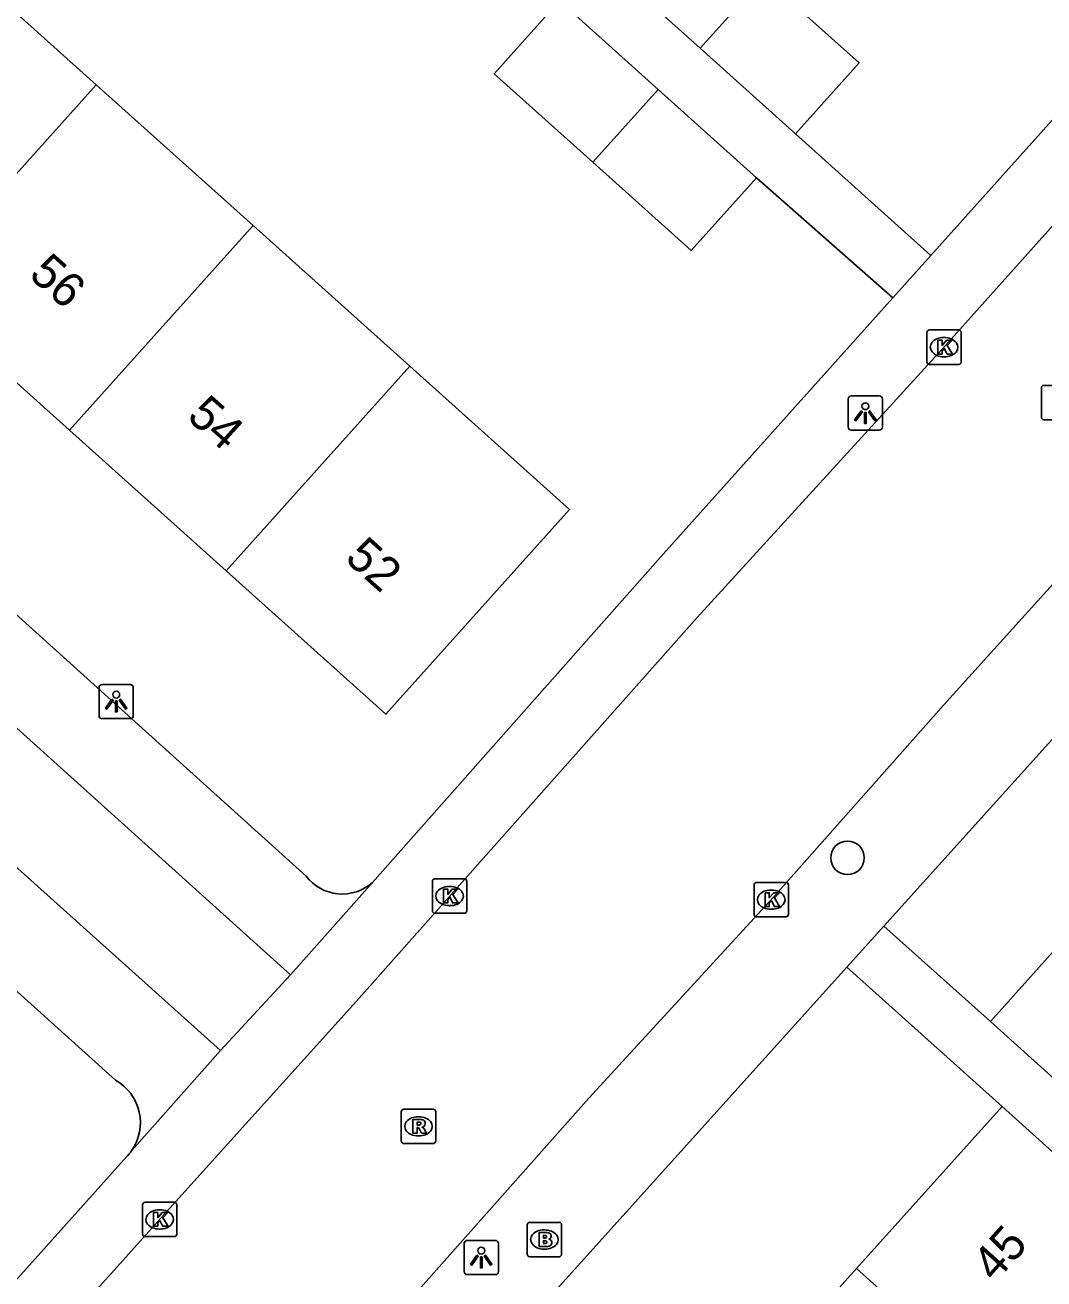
# Model space of a CAD drawing. Extents: x 159040 to 160094, y 381214 to 382518.
# Drawn here: x 159439.83 to 159469.45, y 382064.07 to 382100.53 of the extents above; entities that cross this region are included whole.
import ezdxf

# ---------------------------------------------------------------- set-up
doc = ezdxf.new("R2010")
doc.units = 0
for name, color, linetype in [('IMGEO_Boom', 7, 'Continuous'), ('IMGEO_Brandkraan', 7, 'Continuous'), ('IMGEO_Kolk', 7, 'Continuous'), ('IMGEO_Lichtpunt', 7, 'Continuous'), ('IMGEO_Pand', 7, 'Continuous'), ('IMGEO_Pand_nummerreeks', 7, 'Continuous'), ('IMGEO_Rijbaan_lokaal_open', 7, 'Continuous'), ('IMGEO_Rioolput', 7, 'Continuous'), ('IMGEO_Voetpad_open', 7, 'Continuous')]:
    doc.layers.add(name, color=color, linetype=linetype)

msp = doc.modelspace()

# ---------------------------------------------------------------- linework, layer by layer
at = {"layer": 'IMGEO_Boom'}
msp.add_circle((159463.742, 382076.312), 0.489, dxfattribs=at)
at = {"layer": 'IMGEO_Brandkraan'}
for p, q in [((159454.427, 382064.787), (159454.427, 382065.639)), ((159454.502, 382065.713), (159455.354, 382065.713)), ((159455.428, 382065.639), (159455.428, 382064.787)), ((159454.915, 382065.493), (159454.94, 382065.493)), ((159454.938, 382064.933), (159454.913, 382064.933)), ((159455.354, 382064.713), (159454.502, 382064.713))]:
    msp.add_line(p, q, dxfattribs=at)
for points in [[(159454.427, 382064.787), (159454.427, 382065.639)], [(159454.502, 382065.713), (159455.354, 382065.713)], [(159455.428, 382065.639), (159455.428, 382064.787)], [(159454.775, 382065.413), (159454.775, 382065.013), (159454.988, 382065.013)], [(159455.006, 382065.413), (159454.775, 382065.413)], [(159454.954, 382065.332), (159454.9, 382065.332), (159454.9, 382065.256)], [(159454.9, 382065.256), (159454.953, 382065.256)], [(159454.962, 382065.18), (159454.9, 382065.18), (159454.9, 382065.099)], [(159454.9, 382065.099), (159454.962, 382065.099)], [(159455.354, 382064.713), (159454.502, 382064.713)]]:
    msp.add_lwpolyline(points, dxfattribs=at)
for centre, radius, start, end in [((159454.504, 382065.637), 0.0765, 91.552, 178.448), ((159454.504, 382065.637), 0.0765, 91.552, 178.448), ((159455.352, 382065.637), 0.0765, 1.552, 88.448), ((159455.352, 382065.637), 0.0765, 1.552, 88.448), ((159454.955, 382065.294), 0.0379, 267.8285, 90.9355), ((159455.01, 382065.268), 0.145, 59.4692, 91.5367), ((159455.035, 382065.315), 0.0922, 285.5137, 58.1501), ((159455.04, 382065.123), 0.105, 301.3115, 78.989), ((159454.963, 382065.139), 0.0404, 269.8759, 90.5077), ((159454.994, 382065.264), 0.251, 268.6676, 293.5347), ((159454.504, 382064.789), 0.0765, 181.552, 268.448), ((159454.504, 382064.789), 0.0765, 181.552, 268.448), ((159455.352, 382064.789), 0.0765, 271.552, 358.448), ((159455.352, 382064.789), 0.0765, 271.552, 358.448)]:
    msp.add_arc(centre, radius, start, end, dxfattribs=at)
for centre, major_axis, ratio, start_param, end_param in [((159454.914, 382065.213), (-0.387, 0.002), 0.722429, 4.712389, 7.853982), ((159454.939, 382065.213), (-0.39, 0.002), 0.717154, 1.570796, 4.712389)]:
    msp.add_ellipse(centre, major_axis=major_axis, ratio=ratio, start_param=start_param, end_param=end_param, dxfattribs=at)
at = {"layer": 'IMGEO_Kolk'}
for p, q in [((159466.049, 382090.735), (159466.049, 382091.587)), ((159466.124, 382091.661), (159466.976, 382091.661)), ((159466.537, 382091.441), (159466.562, 382091.441)), ((159467.05, 382091.587), (159467.05, 382090.735)), ((159466.56, 382090.881), (159466.535, 382090.881)), ((159466.976, 382090.661), (159466.124, 382090.661)), ((159451.671, 382074.775), (159451.671, 382075.627)), ((159451.746, 382075.701), (159452.598, 382075.701)), ((159452.159, 382075.481), (159452.184, 382075.481)), ((159452.672, 382075.627), (159452.672, 382074.775)), ((159461.023, 382074.67), (159461.023, 382075.522)), ((159461.098, 382075.596), (159461.95, 382075.596)), ((159462.024, 382075.522), (159462.024, 382074.67)), ((159461.511, 382075.376), (159461.536, 382075.376)), ((159452.598, 382074.701), (159451.746, 382074.701)), ((159452.182, 382074.921), (159452.157, 382074.921)), ((159461.534, 382074.816), (159461.509, 382074.816)), ((159461.95, 382074.596), (159461.098, 382074.596)), ((159443.314, 382066.297), (159444.166, 382066.297)), ((159443.239, 382065.371), (159443.239, 382066.223)), ((159443.727, 382066.077), (159443.752, 382066.077)), ((159444.24, 382066.223), (159444.24, 382065.371)), ((159444.166, 382065.297), (159443.314, 382065.297)), ((159443.75, 382065.517), (159443.725, 382065.517))]:
    msp.add_line(p, q, dxfattribs=at)
for points in [[(159466.049, 382090.735), (159466.049, 382091.587)], [(159466.124, 382091.661), (159466.976, 382091.661)], [(159467.05, 382091.587), (159467.05, 382090.735)], [(159466.37, 382091.361), (159466.493, 382091.361), (159466.493, 382091.21), (159466.623, 382091.361), (159466.787, 382091.361), (159466.641, 382091.21), (159466.794, 382090.961), (159466.642, 382090.961), (159466.557, 382091.125), (159466.493, 382091.058), (159466.493, 382090.961), (159466.37, 382090.961), (159466.37, 382091.361)], [(159466.976, 382090.661), (159466.124, 382090.661)], [(159451.671, 382074.775), (159451.671, 382075.627)], [(159451.746, 382075.701), (159452.598, 382075.701)], [(159451.992, 382075.401), (159452.115, 382075.401), (159452.115, 382075.25), (159452.245, 382075.401), (159452.409, 382075.401), (159452.263, 382075.25), (159452.416, 382075.001), (159452.264, 382075.001), (159452.179, 382075.165), (159452.115, 382075.098), (159452.115, 382075.001), (159451.992, 382075.001), (159451.992, 382075.401)], [(159452.672, 382075.627), (159452.672, 382074.775)], [(159461.023, 382074.67), (159461.023, 382075.522)], [(159461.098, 382075.596), (159461.95, 382075.596)], [(159462.024, 382075.522), (159462.024, 382074.67)], [(159461.344, 382075.296), (159461.467, 382075.296), (159461.467, 382075.145), (159461.597, 382075.296), (159461.761, 382075.296), (159461.615, 382075.145), (159461.768, 382074.896), (159461.616, 382074.896), (159461.531, 382075.06), (159461.467, 382074.993), (159461.467, 382074.896), (159461.344, 382074.896), (159461.344, 382075.296)], [(159452.598, 382074.701), (159451.746, 382074.701)], [(159461.95, 382074.596), (159461.098, 382074.596)], [(159443.314, 382066.297), (159444.166, 382066.297)], [(159443.239, 382065.371), (159443.239, 382066.223)], [(159443.56, 382065.997), (159443.683, 382065.997), (159443.683, 382065.846), (159443.813, 382065.997), (159443.977, 382065.997), (159443.831, 382065.846), (159443.984, 382065.597), (159443.832, 382065.597), (159443.747, 382065.761), (159443.683, 382065.694), (159443.683, 382065.597), (159443.56, 382065.597), (159443.56, 382065.997)], [(159444.24, 382066.223), (159444.24, 382065.371)], [(159444.166, 382065.297), (159443.314, 382065.297)]]:
    msp.add_lwpolyline(points, dxfattribs=at)
for centre, start, end in [((159466.126, 382091.585), 91.552, 178.448), ((159466.126, 382091.585), 91.552, 178.448), ((159466.974, 382091.585), 1.552, 88.448), ((159466.974, 382091.585), 1.552, 88.448), ((159466.126, 382090.737), 181.552, 268.448), ((159466.126, 382090.737), 181.552, 268.448), ((159466.974, 382090.737), 271.552, 358.448), ((159466.974, 382090.737), 271.552, 358.448), ((159451.748, 382075.625), 91.552, 178.448), ((159451.748, 382075.625), 91.552, 178.448), ((159452.596, 382075.625), 1.552, 88.448), ((159452.596, 382075.625), 1.552, 88.448), ((159461.1, 382075.52), 91.552, 178.448), ((159461.1, 382075.52), 91.552, 178.448), ((159461.948, 382075.52), 1.552, 88.448), ((159461.948, 382075.52), 1.552, 88.448), ((159451.748, 382074.777), 181.552, 268.448), ((159451.748, 382074.777), 181.552, 268.448), ((159452.596, 382074.777), 271.552, 358.448), ((159452.596, 382074.777), 271.552, 358.448), ((159461.1, 382074.672), 181.552, 268.448), ((159461.1, 382074.672), 181.552, 268.448), ((159461.948, 382074.672), 271.552, 358.448), ((159461.948, 382074.672), 271.552, 358.448), ((159443.316, 382066.221), 91.552, 178.448), ((159443.316, 382066.221), 91.552, 178.448), ((159444.164, 382066.221), 1.552, 88.448), ((159444.164, 382066.221), 1.552, 88.448), ((159443.316, 382065.373), 181.552, 268.448), ((159443.316, 382065.373), 181.552, 268.448), ((159444.164, 382065.373), 271.552, 358.448), ((159444.164, 382065.373), 271.552, 358.448)]:
    msp.add_arc(centre, 0.0765, start, end, dxfattribs=at)
for centre, major_axis, ratio, start_param, end_param in [((159466.536, 382091.161), (-0.387, 0.002), 0.722429, 4.712389, 7.853982), ((159466.561, 382091.161), (-0.39, 0.002), 0.717154, 1.570796, 4.712389), ((159452.158, 382075.201), (-0.387, 0.002), 0.722429, 4.712389, 7.853982), ((159452.183, 382075.201), (-0.39, 0.002), 0.717154, 1.570796, 4.712389), ((159461.51, 382075.096), (-0.387, 0.002), 0.722429, 4.712389, 7.853982), ((159461.535, 382075.096), (-0.39, 0.002), 0.717154, 1.570796, 4.712389), ((159443.726, 382065.797), (-0.387, 0.002), 0.722429, 4.712389, 7.853982), ((159443.751, 382065.797), (-0.39, 0.002), 0.717154, 1.570796, 4.712389)]:
    msp.add_ellipse(centre, major_axis=major_axis, ratio=ratio, start_param=start_param, end_param=end_param, dxfattribs=at)
at = {"layer": 'IMGEO_Lichtpunt'}
for p, q in [((159463.762, 382089.647), (159463.762, 382088.84)), ((159463.762, 382089.647), (159463.762, 382088.84)), ((159464.664, 382089.742), (159463.856, 382089.742)), ((159464.664, 382089.742), (159463.856, 382089.742)), ((159464.758, 382088.84), (159464.758, 382089.647)), ((159464.758, 382088.84), (159464.758, 382089.647)), ((159463.856, 382088.746), (159464.664, 382088.746)), ((159463.856, 382088.746), (159464.664, 382088.746)), ((159441.977, 382081.26), (159441.977, 382080.453)), ((159441.977, 382081.26), (159441.977, 382080.453)), ((159442.879, 382081.355), (159442.071, 382081.355)), ((159442.879, 382081.355), (159442.071, 382081.355)), ((159442.973, 382080.453), (159442.973, 382081.26)), ((159442.973, 382080.453), (159442.973, 382081.26)), ((159442.071, 382080.359), (159442.879, 382080.359)), ((159442.071, 382080.359), (159442.879, 382080.359)), ((159453.495, 382065.188), (159452.687, 382065.188)), ((159453.495, 382065.188), (159452.687, 382065.188)), ((159452.593, 382065.093), (159452.593, 382064.286)), ((159452.593, 382065.093), (159452.593, 382064.286)), ((159453.589, 382064.286), (159453.589, 382065.093)), ((159453.589, 382064.286), (159453.589, 382065.093)), ((159452.687, 382064.192), (159453.495, 382064.192)), ((159452.687, 382064.192), (159453.495, 382064.192))]:
    msp.add_line(p, q, dxfattribs=at)
for points in [[(159464.136, 382089.311), (159464.175, 382089.283), (159463.987, 382089.021), (159463.949, 382089.048), (159464.136, 382089.311)], [(159464.238, 382089.263), (159464.285, 382089.263), (159464.285, 382088.941), (159464.238, 382088.941), (159464.238, 382089.263)], [(159464.348, 382089.283), (159464.386, 382089.31), (159464.573, 382089.048), (159464.534, 382089.02), (159464.348, 382089.283)], [(159442.351, 382080.924), (159442.39, 382080.896), (159442.202, 382080.634), (159442.164, 382080.661), (159442.351, 382080.924)], [(159442.453, 382080.876), (159442.5, 382080.876), (159442.5, 382080.554), (159442.453, 382080.554), (159442.453, 382080.876)], [(159442.563, 382080.896), (159442.601, 382080.923), (159442.788, 382080.661), (159442.749, 382080.633), (159442.563, 382080.896)], [(159452.967, 382064.757), (159453.006, 382064.729), (159452.818, 382064.467), (159452.78, 382064.494), (159452.967, 382064.757)], [(159453.069, 382064.709), (159453.116, 382064.709), (159453.116, 382064.387), (159453.069, 382064.387), (159453.069, 382064.709)], [(159453.179, 382064.729), (159453.217, 382064.756), (159453.404, 382064.494), (159453.365, 382064.466), (159453.179, 382064.729)]]:
    msp.add_lwpolyline(points, dxfattribs=at)
for centre in [(159464.261, 382089.445), (159442.476, 382081.058), (159453.092, 382064.891)]:
    msp.add_circle(centre, 0.0994, dxfattribs=at)
for centre, start, end in [((159463.856, 382089.647), 90, 180), ((159463.856, 382089.647), 90, 180), ((159464.664, 382089.647), 0, 90), ((159464.664, 382089.647), 0, 90), ((159463.856, 382088.84), 180, 270), ((159463.856, 382088.84), 180, 270), ((159464.664, 382088.84), 270, 0), ((159464.664, 382088.84), 270, 360), ((159442.071, 382081.26), 90, 180), ((159442.071, 382081.26), 90, 180), ((159442.879, 382081.26), 0, 90), ((159442.879, 382081.26), 0, 90), ((159442.071, 382080.453), 180, 270), ((159442.071, 382080.453), 180, 270), ((159442.879, 382080.453), 270, 0), ((159442.879, 382080.453), 270, 360), ((159452.687, 382065.093), 90, 180), ((159452.687, 382065.093), 90, 180), ((159453.495, 382065.093), 0, 90), ((159453.495, 382065.093), 0, 90), ((159452.687, 382064.286), 180, 270), ((159452.687, 382064.286), 180, 270), ((159453.495, 382064.286), 270, 0), ((159453.495, 382064.286), 270, 360)]:
    msp.add_arc(centre, 0.0946, start, end, dxfattribs=at)
at = {"layer": 'IMGEO_Pand'}
for points in [[(159437.336, 382102.884), (159441.895, 382098.793)], [(159459.458, 382099.852), (159456.432, 382102.566)], [(159461.309, 382101.914), (159459.458, 382099.852)], [(159461.309, 382101.914), (159464.079, 382099.428), (159462.228, 382097.366)], [(159456.334, 382096.537), (159453.463, 382099.114), (159455.363, 382101.231)], [(159455.363, 382101.231), (159458.235, 382098.654)], [(159462.228, 382097.366), (159459.458, 382099.852)], [(159436.554, 382092.841), (159441.895, 382098.793)], [(159441.895, 382098.793), (159446.455, 382094.7)], [(159458.235, 382098.654), (159456.334, 382096.537)], [(159458.235, 382098.654), (159461.093, 382096.089)], [(159461.093, 382096.089), (159459.193, 382093.971), (159456.334, 382096.537)], [(159446.455, 382094.7), (159441.114, 382088.749)], [(159446.455, 382094.7), (159451.014, 382090.609)], [(159441.114, 382088.749), (159436.554, 382092.841)], [(159451.014, 382090.609), (159455.662, 382086.437), (159450.321, 382080.486), (159445.673, 382084.658)], [(159451.014, 382090.609), (159445.673, 382084.658)], [(159445.673, 382084.658), (159441.114, 382088.749)], [(159467.896, 382071.551), (159472.072, 382076.204)], [(159473.94, 382066.126), (159471.617, 382068.211), (159467.896, 382071.551)], [(159464.008, 382064.367), (159468.237, 382069.079)], [(159468.237, 382069.079), (159471.956, 382065.74), (159473.11, 382064.705)], [(159459.858, 382059.743), (159464.008, 382064.367)], [(159468.88, 382059.992), (159464.008, 382064.367)]]:
    msp.add_lwpolyline(points, dxfattribs=at)
at = {"layer": 'IMGEO_Rijbaan_lokaal_open'}
for points in [[(159484.51, 382111.174), (159481.021, 382107.349), (159474.838, 382100.428), (159466.594, 382091.206), (159459.375, 382083.3), (159449.46, 382072.146), (159446.424, 382068.776), (159443.761, 382065.82), (159436.593, 382057.833), (159429.233, 382049.65), (159421.179, 382040.701), (159414.041, 382032.697), (159412.333, 382030.791)], [(159417.471, 382026.041), (159418.427, 382027.145), (159421.101, 382030.063), (159436.695, 382047.561), (159444.758, 382056.431), (159447.825, 382059.867), (159456.22, 382069.32), (159461.578, 382075.157), (159466.546, 382080.765), (159473.262, 382088.194), (159486.13, 382102.405), (159490.537, 382107.476)], [(159421.139, 382094.706), (159422.172, 382095.85), (159426.476, 382091.859), (159439.286, 382080.355), (159447.544, 382072.913)], [(159421.139, 382094.706), (159420.122, 382093.578), (159424.405, 382089.668), (159432.474, 382082.409), (159445.513, 382070.713)], [(159447.544, 382072.913), (159445.513, 382070.713)]]:
    msp.add_lwpolyline(points, dxfattribs=at)
at = {"layer": 'IMGEO_Rioolput'}
for p, q in [((159469.379, 382089.125), (159469.379, 382089.977)), ((159469.454, 382090.051), (159470.306, 382090.051)), ((159470.306, 382089.051), (159469.454, 382089.051)), ((159450.766, 382068.078), (159450.766, 382068.93)), ((159450.841, 382069.004), (159451.693, 382069.004)), ((159451.767, 382068.93), (159451.767, 382068.078)), ((159451.254, 382068.784), (159451.279, 382068.784)), ((159451.277, 382068.224), (159451.252, 382068.224)), ((159451.693, 382068.004), (159450.841, 382068.004))]:
    msp.add_line(p, q, dxfattribs=at)
for points in [[(159469.379, 382089.125), (159469.379, 382089.977)], [(159469.454, 382090.051), (159470.306, 382090.051)], [(159470.306, 382089.051), (159469.454, 382089.051)], [(159450.766, 382068.078), (159450.766, 382068.93)], [(159450.841, 382069.004), (159451.693, 382069.004)], [(159451.767, 382068.93), (159451.767, 382068.078)], [(159451.355, 382068.702), (159451.103, 382068.704), (159451.103, 382068.304)], [(159451.103, 382068.304), (159451.227, 382068.304), (159451.227, 382068.466), (159451.238, 382068.466)], [(159451.281, 382068.623), (159451.227, 382068.623), (159451.227, 382068.542)], [(159451.227, 382068.542), (159451.279, 382068.542)], [(159451.285, 382068.437), (159451.356, 382068.304), (159451.496, 382068.304), (159451.431, 382068.43)], [(159451.693, 382068.004), (159450.841, 382068.004)]]:
    msp.add_lwpolyline(points, dxfattribs=at)
for centre, radius, start, end in [((159469.456, 382089.975), 0.0765, 91.552, 178.448), ((159469.456, 382089.975), 0.0765, 91.552, 178.448), ((159469.456, 382089.127), 0.0765, 181.552, 268.448), ((159469.456, 382089.127), 0.0765, 181.552, 268.448), ((159450.843, 382068.928), 0.0765, 91.552, 178.448), ((159450.843, 382068.928), 0.0765, 91.552, 178.448), ((159451.691, 382068.928), 0.0765, 1.552, 88.448), ((159451.691, 382068.928), 0.0765, 1.552, 88.448), ((159451.237, 382068.413), 0.0533, 26.0293, 88.6989), ((159451.263, 382068.731), 0.19, 274.7715, 282.9687), ((159451.287, 382068.527), 0.0964, 77.0061, 93.1865), ((159451.301, 382068.584), 0.0378, 276.6634, 79.6772), ((159451.354, 382068.592), 0.109, 350.3612, 89.416), ((159451.352, 382068.592), 0.112, 277.5842, 350.9817), ((159451.336, 382068.377), 0.108, 29.5134, 73.7905), ((159450.843, 382068.08), 0.0765, 181.552, 268.448), ((159450.843, 382068.08), 0.0765, 181.552, 268.448), ((159451.691, 382068.08), 0.0765, 271.552, 358.448), ((159451.691, 382068.08), 0.0765, 271.552, 358.448)]:
    msp.add_arc(centre, radius, start, end, dxfattribs=at)
for centre, major_axis, ratio, start_param, end_param in [((159451.253, 382068.504), (-0.387, 0.002), 0.722429, 4.712389, 7.853982), ((159451.278, 382068.504), (-0.39, 0.002), 0.717154, 1.570796, 4.712389)]:
    msp.add_ellipse(centre, major_axis=major_axis, ratio=ratio, start_param=start_param, end_param=end_param, dxfattribs=at)
at = {"layer": 'IMGEO_Voetpad_open'}
for points in [[(159466.167, 382093.83), (159480.109, 382109.39)], [(159464.803, 382074.327), (159490.855, 382103.242)], [(159424.019, 382097.413), (159447.998, 382075.782)], [(159466.167, 382093.83), (159462.228, 382097.366)], [(159461.093, 382096.089), (159465.06, 382092.595)], [(159465.06, 382092.595), (159466.167, 382093.83)], [(159449.93, 382075.598), (159458.384, 382085.144), (159465.06, 382092.595)], [(159442.459, 382069.847), (159418.503, 382091.427), (159418.239, 382091.137)], [(159449.93, 382075.598), (159447.544, 382072.913)], [(159463.725, 382073.13), (159464.803, 382074.327)], [(159464.803, 382074.327), (159467.896, 382071.551)], [(159446.933, 382054.493), (159463.725, 382073.13)], [(159468.237, 382069.079), (159463.725, 382073.13)], [(159445.513, 382070.713), (159442.922, 382067.79)], [(159442.778, 382067.615), (159427.974, 382051.104)]]:
    msp.add_lwpolyline(points, dxfattribs=at)
for centre, radius, start, end in [((159449.048, 382076.575), 1.316, 217.0622, 312.0572), ((159441.749, 382068.607), 1.429, 325.1415, 60.2286), ((159441.582, 382068.746), 1.646, 316.603, 324.498)]:
    msp.add_arc(centre, radius, start, end, dxfattribs=at)

# ---------------------------------------------------------------- texts
at = {"layer": 'IMGEO_Pand_nummerreeks'}
for s, rotation, p in [('56', 318.0947, (159439.901, 382093.223)), ('54', 318.0947, (159444.496, 382089.099)), ('52', 318.0947, (159449.089, 382084.977)), ('45', 48.0928, (159468.032, 382063.939))]:
    msp.add_text(s, height=1, rotation=rotation, dxfattribs=at).set_placement(p)

doc.saveas('drawing.dxf')
